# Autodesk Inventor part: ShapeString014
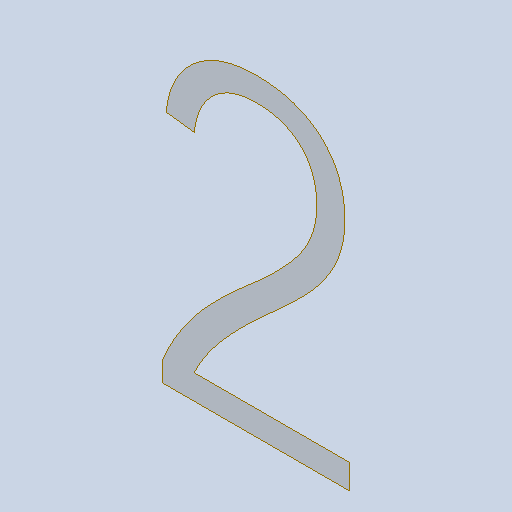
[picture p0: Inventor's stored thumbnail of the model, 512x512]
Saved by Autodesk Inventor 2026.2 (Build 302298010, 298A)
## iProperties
Created: 2026-10
Part Number: ShapeString014
Material: Générique
Document SubType Name: Modeling
Designer: mel
Density: 1 g/cm^3
Appearance: Par défaut
Author: mel
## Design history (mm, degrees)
feature "Composite1"
body "Srf1"
